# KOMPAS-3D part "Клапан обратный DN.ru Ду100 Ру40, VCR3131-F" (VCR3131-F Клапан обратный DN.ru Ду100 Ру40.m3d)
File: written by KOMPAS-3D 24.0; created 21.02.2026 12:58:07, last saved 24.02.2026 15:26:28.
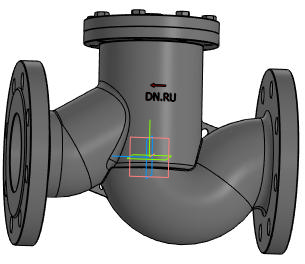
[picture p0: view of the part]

Document properties: Автор: R2D2; Полное имя файла: VCR3131-F Клапан обратный DN.ru Ду100 Ру40.cdw

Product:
- Part/product: Клапан обратный DN.ru Ду100 Ру40  | designation VCR3131-F
    Масса: 26.5
    Раздел спецификации: Прочие изделия
    Форматы листов документа: A2
    Примечание: D100-04044
    additional columns: D100-04044

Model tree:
1. Операция без истории:1

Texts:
  VCR3131-F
